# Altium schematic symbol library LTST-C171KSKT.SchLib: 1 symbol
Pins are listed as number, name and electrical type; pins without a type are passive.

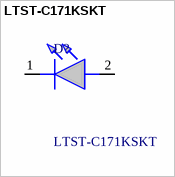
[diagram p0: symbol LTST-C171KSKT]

## LTST-C171KSKT
designator D?
Yellow 587nm LED Indication - Discrete 2V 0805 (2012 Metric); Manufacturer_Name: Lite-On; Geometry.Height: 0.9mm
footprint LTSTC171KSKT
pins: 1 K, 2 A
